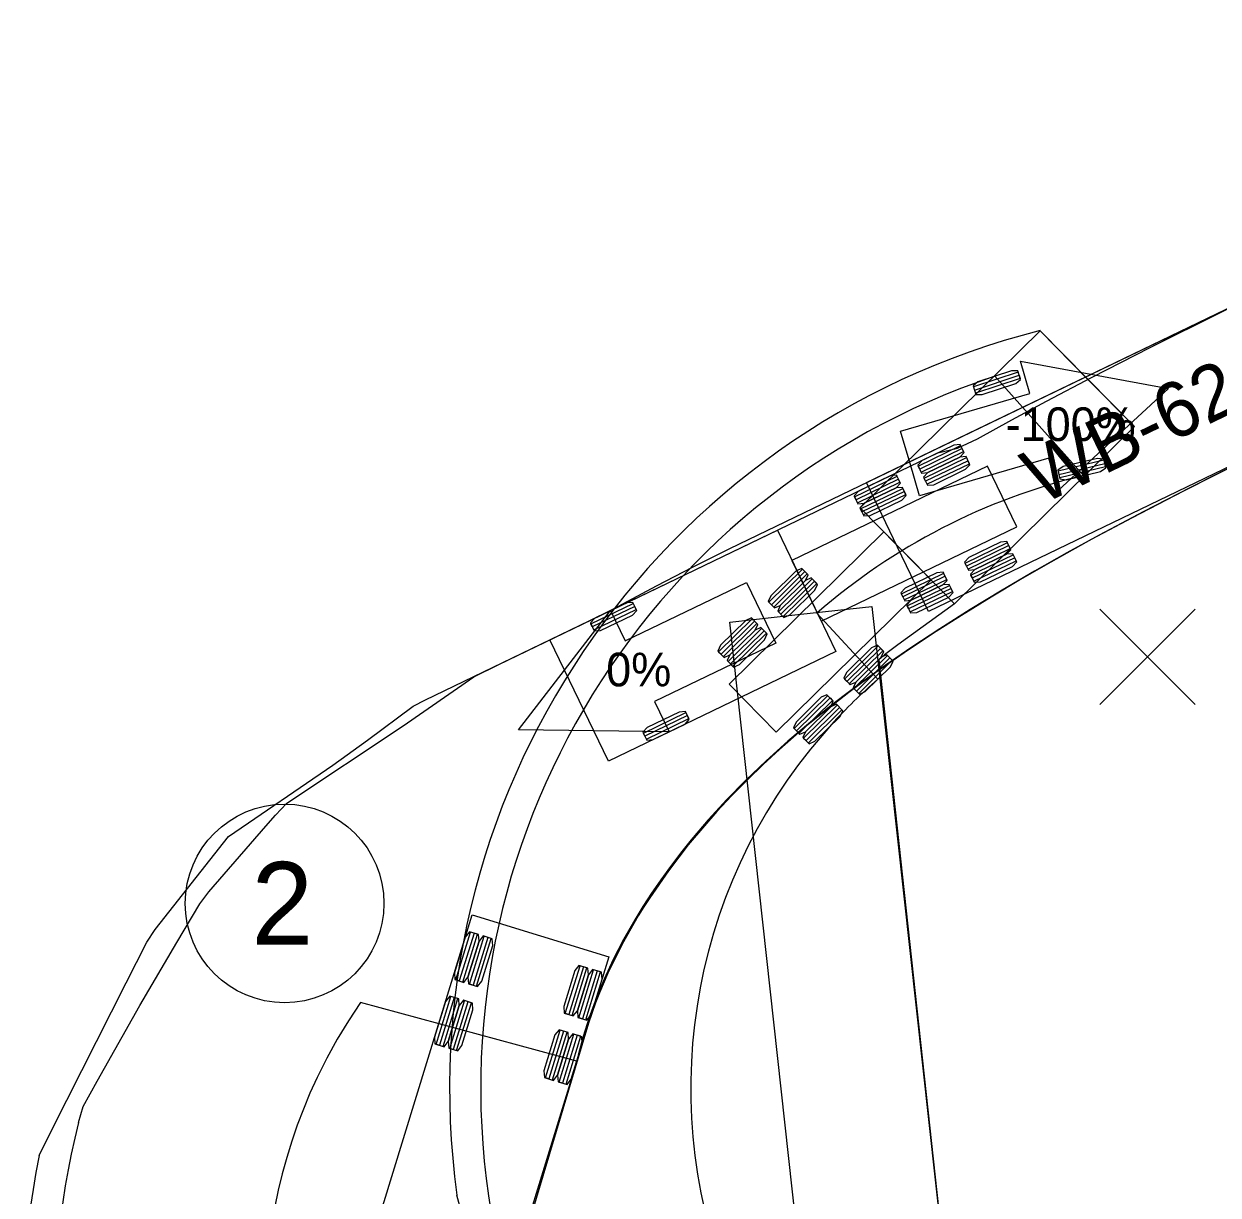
# Model space of a CAD drawing. Extents: x 1475900 to 1484331, y 375914 to 383395.
# Drawn here: x 1478701.4 to 1478772.4, y 379939.6 to 380009.2 of the extents above; entities that cross this region are included whole.
import ezdxf

# ---------------------------------------------------------------- set-up
doc = ezdxf.new("R2010")
doc.units = 0
doc.layers.add('PM_X_Misc', color=7, linetype='Continuous')
doc.layers.add('PM_X_Misc (Construction)', color=7, linetype='Continuous')

# ---------------------------------------------------------------- blocks, each defined once
blk = doc.blocks.new('ATRPTH_1')
at = {"layer": 'PM_X_Misc'}
for points in [[(375830.738, 96498.58), (375830.934, 96498.976), (375832.049, 96501.184), (375832.363, 96501.8), (375832.488, 96501.988), (375833.598, 96503.394), (375835.173, 96504.471), (375835.692, 96504.85), (375836.386, 96505.363), (375836.572, 96505.458), (375839.334, 96506.789), (375840.056, 96507.179), (375840.608, 96507.466), (375841.162, 96507.741), (375854.209, 96514.03), (375855.146, 96512.085)], [(375843.226, 96508.736), (375854.209, 96514.03), (375854.677, 96513.058), (375855.146, 96512.085), (375844.164, 96506.791), (375843.695, 96507.763), (375843.226, 96508.736), (375843.226, 96508.736)], [(375831.333, 96499.078), (375831.4, 96499.318), (375831.611, 96499.7), (375832.258, 96500.842), (375832.814, 96501.795), (375833.161, 96502.378), (375833.297, 96502.56), (375834.16, 96503.55), (375834.306, 96503.716), (375834.474, 96503.896), (375836.234, 96505.064), (375837.299, 96505.804), (375837.675, 96505.989), (375844.306, 96509.186), (375844.598, 96509.254), (375844.902, 96509.394), (375845.422, 96509.684), (375845.942, 96509.965), (375846.631, 96510.327), (375847.509, 96510.775), (375848.583, 96511.308), (375849.894, 96511.949), (375853.637, 96513.754), (375854.574, 96511.809)], [(375848.95, 96509.08), (375848.013, 96508.607), (375847.235, 96508.204), (375846.62, 96507.875), (375846.01, 96507.536), (375845.554, 96507.273), (375845.108, 96507.008), (375844.662, 96506.732), (375844.224, 96506.454), (375843.794, 96506.165), (375843.369, 96505.869), (375842.958, 96505.566), (375842.423, 96505.144), (375842.293, 96505.038), (375841.913, 96504.707), (375841.668, 96504.483), (375841.429, 96504.25), (375841.195, 96504.015), (375840.97, 96503.773), (375840.536, 96503.27), (375840.236, 96502.876), (375839.956, 96502.47), (375839.866, 96502.334), (375839.78, 96502.197), (375839.539, 96501.77), (375839.324, 96501.332), (375839.197, 96501.033), (375839.138, 96500.883), (375839.032, 96500.576), (375836.07, 96490.664)], [(375849.002, 96509.107), (375848.11, 96508.658), (375847.411, 96508.299), (375846.741, 96507.943), (375846.251, 96507.675), (375845.761, 96507.398), (375845.276, 96507.114), (375844.794, 96506.821), (375844.333, 96506.53), (375843.913, 96506.254), (375843.508, 96505.976), (375843.117, 96505.694), (375842.742, 96505.409), (375842.383, 96505.122), (375842.04, 96504.831), (375841.714, 96504.538), (375841.405, 96504.243), (375841.113, 96503.945), (375840.839, 96503.645), (375840.582, 96503.345), (375840.42, 96503.144), (375840.267, 96502.942), (375840.12, 96502.741), (375839.982, 96502.539), (375839.851, 96502.338), (375839.728, 96502.138), (375839.557, 96501.837), (375839.404, 96501.539), (375839.266, 96501.243), (375839.145, 96500.95), (375839.04, 96500.66), (375838.95, 96500.374), (375838.875, 96500.093), (375838.854, 96500.001), (375835.587, 96500.888), (375835.406, 96500.614), (375835.237, 96500.334), (375835.08, 96500.048), (375834.934, 96499.756)], [(375844.052, 96508.894), (375844.693, 96509.203), (375844.671, 96509.249), (375844.03, 96508.94), (375844.008, 96508.986), (375844.648, 96509.295), (375844.641, 96509.31), (375844.546, 96509.302), (375844.066, 96509.07), (375844, 96509.001), (375844.059, 96508.879), (375844.154, 96508.887), (375844.635, 96509.119), (375844.7, 96509.188), (375844.641, 96509.31)], [(375844.14, 96508.711), (375844.781, 96509.02), (375844.759, 96509.066), (375844.118, 96508.757), (375844.096, 96508.803), (375844.737, 96509.112), (375844.729, 96509.127), (375844.635, 96509.119), (375844.154, 96508.887), (375844.089, 96508.818), (375844.148, 96508.696), (375844.242, 96508.704), (375844.723, 96508.936), (375844.788, 96509.005), (375844.729, 96509.127)], [(375842.543, 96506.644), (375845.494, 96508.067), (375845.053, 96508.982), (375842.101, 96507.559), (375842.543, 96506.644)], [(375843.091, 96508.431), (375843.732, 96508.74), (375843.71, 96508.786), (375843.069, 96508.477), (375843.047, 96508.523), (375843.688, 96508.831), (375843.68, 96508.847), (375843.585, 96508.839), (375843.105, 96508.607), (375843.039, 96508.538), (375843.098, 96508.416), (375843.193, 96508.424), (375843.674, 96508.655), (375843.739, 96508.725), (375843.68, 96508.847)], [(375843.179, 96508.248), (375843.82, 96508.557), (375843.798, 96508.603), (375843.157, 96508.294), (375843.135, 96508.339), (375843.776, 96508.648), (375843.768, 96508.664), (375843.674, 96508.655), (375843.193, 96508.424), (375843.128, 96508.355), (375843.187, 96508.233), (375843.281, 96508.241), (375843.762, 96508.472), (375843.827, 96508.542), (375843.768, 96508.664)], [(375838.449, 96506.362), (375841.881, 96508.017), (375842.763, 96506.186), (375839.331, 96504.532), (375838.89, 96505.447), (375838.449, 96506.362), (375838.449, 96506.362)], [(375844.758, 96507.43), (375845.398, 96507.739), (375845.376, 96507.784), (375844.736, 96507.476), (375844.714, 96507.521), (375845.354, 96507.83), (375845.347, 96507.846), (375845.252, 96507.837), (375844.772, 96507.606), (375844.706, 96507.537), (375844.765, 96507.415), (375844.86, 96507.423), (375845.34, 96507.654), (375845.406, 96507.723), (375845.347, 96507.846)], [(375844.846, 96507.247), (375845.487, 96507.556), (375845.465, 96507.601), (375844.824, 96507.293), (375844.802, 96507.338), (375845.443, 96507.647), (375845.435, 96507.662), (375845.34, 96507.654), (375844.86, 96507.423), (375844.795, 96507.354), (375844.853, 96507.232), (375844.948, 96507.24), (375845.429, 96507.471), (375845.494, 96507.54), (375845.435, 96507.662)], [(375843.797, 96506.967), (375844.438, 96507.275), (375844.415, 96507.321), (375843.775, 96507.012), (375843.753, 96507.058), (375844.393, 96507.367), (375844.386, 96507.382), (375844.291, 96507.374), (375843.811, 96507.143), (375843.745, 96507.073), (375843.804, 96506.951), (375843.899, 96506.96), (375844.379, 96507.191), (375844.445, 96507.26), (375844.386, 96507.382)], [(375843.885, 96506.784), (375844.526, 96507.092), (375844.504, 96507.138), (375843.863, 96506.829), (375843.841, 96506.875), (375844.482, 96507.184), (375844.474, 96507.199), (375844.379, 96507.191), (375843.899, 96506.96), (375843.834, 96506.89), (375843.892, 96506.768), (375843.987, 96506.776), (375844.468, 96507.008), (375844.533, 96507.077), (375844.474, 96507.199)], [(375839.11, 96506.512), (375839.75, 96506.821), (375839.728, 96506.866), (375839.088, 96506.558), (375839.066, 96506.603), (375839.706, 96506.912), (375839.699, 96506.927), (375839.604, 96506.919), (375839.124, 96506.688), (375839.058, 96506.619), (375839.117, 96506.497), (375839.212, 96506.505), (375839.692, 96506.736), (375839.758, 96506.805), (375839.699, 96506.927)], [(375839.904, 96504.864), (375840.545, 96505.173), (375840.523, 96505.219), (375839.882, 96504.91), (375839.86, 96504.956), (375840.5, 96505.265), (375840.493, 96505.28), (375840.398, 96505.272), (375839.918, 96505.04), (375839.852, 96504.971), (375839.911, 96504.849), (375840.006, 96504.857), (375840.487, 96505.089), (375840.552, 96505.158), (375840.493, 96505.28)], [(375833.695, 96490.558), (375837.275, 96502.213), (375838.306, 96501.896), (375839.338, 96501.579), (375835.759, 96489.924), (375834.727, 96490.241), (375833.695, 96490.558), (375833.695, 96490.558)], [(375837.132, 96501.197), (375837.354, 96501.919), (375837.302, 96501.935), (375837.08, 96501.213), (375837.029, 96501.229), (375837.251, 96501.951), (375837.233, 96501.956), (375837.171, 96501.877), (375837.005, 96501.335), (375837.012, 96501.234), (375837.149, 96501.192), (375837.211, 96501.271), (375837.378, 96501.813), (375837.371, 96501.914), (375837.233, 96501.956)], [(375837.338, 96501.134), (375837.56, 96501.856), (375837.509, 96501.872), (375837.287, 96501.149), (375837.235, 96501.165), (375837.457, 96501.888), (375837.44, 96501.893), (375837.378, 96501.813), (375837.211, 96501.271), (375837.218, 96501.171), (375837.356, 96501.128), (375837.418, 96501.208), (375837.584, 96501.75), (375837.577, 96501.851), (375837.44, 96501.893)], [(375838.783, 96500.69), (375839.005, 96501.412), (375838.953, 96501.428), (375838.731, 96500.706), (375838.68, 96500.722), (375838.902, 96501.444), (375838.884, 96501.449), (375838.822, 96501.37), (375838.656, 96500.828), (375838.663, 96500.727), (375838.8, 96500.685), (375838.862, 96500.764), (375839.029, 96501.306), (375839.022, 96501.407), (375838.884, 96501.449)], [(375838.989, 96500.627), (375839.211, 96501.349), (375839.16, 96501.365), (375838.938, 96500.642), (375838.886, 96500.658), (375839.108, 96501.381), (375839.091, 96501.386), (375839.029, 96501.306), (375838.862, 96500.764), (375838.869, 96500.664), (375839.007, 96500.621), (375839.069, 96500.701), (375839.235, 96501.243), (375839.228, 96501.344), (375839.091, 96501.386)], [(375836.834, 96500.226), (375837.056, 96500.948), (375837.004, 96500.964), (375836.782, 96500.242), (375836.73, 96500.257), (375836.952, 96500.98), (375836.935, 96500.985), (375836.873, 96500.905), (375836.707, 96500.364), (375836.713, 96500.263), (375836.851, 96500.22), (375836.913, 96500.3), (375837.079, 96500.842), (375837.073, 96500.943), (375836.935, 96500.985)], [(375837.04, 96500.162), (375837.262, 96500.885), (375837.21, 96500.901), (375836.988, 96500.178), (375836.937, 96500.194), (375837.159, 96500.916), (375837.142, 96500.922), (375837.079, 96500.842), (375836.913, 96500.3), (375836.92, 96500.199), (375837.057, 96500.157), (375837.119, 96500.237), (375837.286, 96500.779), (375837.279, 96500.879), (375837.142, 96500.922)], [(375838.485, 96499.719), (375838.707, 96500.441), (375838.655, 96500.457), (375838.433, 96499.735), (375838.382, 96499.75), (375838.603, 96500.473), (375838.586, 96500.478), (375838.524, 96500.398), (375838.358, 96499.857), (375838.364, 96499.756), (375838.502, 96499.713), (375838.564, 96499.793), (375838.73, 96500.335), (375838.724, 96500.436), (375838.586, 96500.478)], [(375838.691, 96499.655), (375838.913, 96500.378), (375838.861, 96500.394), (375838.64, 96499.671), (375838.588, 96499.687), (375838.81, 96500.409), (375838.793, 96500.415), (375838.73, 96500.335), (375838.564, 96499.793), (375838.571, 96499.692), (375838.708, 96499.65), (375838.771, 96499.73), (375838.937, 96500.272), (375838.93, 96500.372), (375838.793, 96500.415)]]:
    blk.add_lwpolyline(points, dxfattribs=at)
for radius, start, end in [(8.159, 154.6205, 211.9328), (11.328, 165.5904, 242.3887), (11.798, 168.6581, 246.6027)]:
    blk.add_arc((375842.305, 96496.259), radius, start, end, dxfattribs=at)
at = {"layer": 'PM_X_Misc (Construction)'}
blk.add_lwpolyline([(375841.636, 96506.771), (375841.856, 96506.313), (375840.026, 96505.431), (375840.246, 96504.973), (375837.975, 96505.006), (375839.364, 96506.804), (375839.585, 96506.346), (375841.415, 96507.228), (375841.636, 96506.771)], dxfattribs=at)
blk.add_circle((375834.443, 96502.384), 1.5, dxfattribs=at)
at = {"layer": 'PM_X_Misc'}
blk.add_text('WB-62 - Interstate Semi-Trailer', height=0.83333, rotation=25.7365, dxfattribs=at).set_placement((375845.858, 96508.39))
at = {"layer": 'PM_X_Misc (Construction)'}
for s, height, p in [('0%', 0.508, (375839.297, 96505.66)), ('2', 1.25, (375833.943, 96501.759))]:
    blk.add_text(s, height=height, dxfattribs=at).set_placement(p)
blk = doc.blocks.new('ATRPTH_4')
at = {"layer": 'PM_X_Misc'}
for p, q in [((375845.162, 96510.34), (375846.501, 96508.841)), ((375842.479, 96506.764), (375843.398, 96505.767)), ((375842.697, 96505.084), (375842.381, 96504.71))]:
    blk.add_line(p, q, dxfattribs=at)
for points in [[(375847.272, 96509.58), (375844.557, 96506.908), (375843.131, 96508.356), (375845.847, 96511.028), (375846.559, 96510.304), (375847.272, 96509.58), (375847.272, 96509.58)], [(375845.847, 96511.028), (375847.272, 96509.58), (375844.557, 96506.908), (375843.698, 96506.286), (375843.5, 96506.134), (375843.411, 96506.061), (375844.536, 96495.758)], [(375845.515, 96510.404), (375844.84, 96510.179), (375844.856, 96510.131), (375845.531, 96510.355), (375845.547, 96510.307), (375844.872, 96510.083), (375844.878, 96510.067), (375844.973, 96510.063), (375845.479, 96510.231), (375845.553, 96510.291), (375845.51, 96510.42), (375845.415, 96510.424), (375844.909, 96510.256), (375844.835, 96510.195), (375844.878, 96510.067)], [(375846.811, 96509.073), (375846.119, 96508.906), (375846.131, 96508.857), (375846.823, 96509.023), (375846.834, 96508.974), (375846.143, 96508.807), (375846.147, 96508.791), (375846.241, 96508.779), (375846.76, 96508.904), (375846.838, 96508.957), (375846.807, 96509.089), (375846.712, 96509.101), (375846.194, 96508.976), (375846.115, 96508.922), (375846.147, 96508.791)], [(375843.488, 96507.994), (375841.153, 96505.695), (375841.865, 96504.971), (375844.201, 96507.27), (375843.488, 96507.994)], [(375842.262, 96507.429), (375841.755, 96506.93), (375841.791, 96506.893), (375842.298, 96507.392), (375842.333, 96507.356), (375841.826, 96506.857), (375841.838, 96506.845), (375841.925, 96506.883), (375842.306, 96507.258), (375842.345, 96507.344), (375842.25, 96507.441), (375842.163, 96507.402), (375841.783, 96507.028), (375841.743, 96506.942), (375841.838, 96506.845)], [(375842.405, 96507.284), (375841.898, 96506.785), (375841.933, 96506.749), (375842.44, 96507.247), (375842.476, 96507.211), (375841.969, 96506.712), (375841.981, 96506.7), (375842.068, 96506.739), (375842.448, 96507.113), (375842.488, 96507.199), (375842.393, 96507.296), (375842.306, 96507.258), (375841.925, 96506.883), (375841.886, 96506.797), (375841.981, 96506.7)], [(375843.309, 96506.866), (375844.644, 96494.748), (375843.571, 96494.629), (375842.498, 96494.511), (375841.163, 96506.63), (375842.236, 96506.748), (375843.309, 96506.866), (375843.309, 96506.866)], [(375841.502, 96506.68), (375840.995, 96506.181), (375841.031, 96506.145), (375841.537, 96506.644), (375841.573, 96506.608), (375841.066, 96506.109), (375841.078, 96506.097), (375841.165, 96506.135), (375841.545, 96506.509), (375841.585, 96506.596), (375841.49, 96506.692), (375841.403, 96506.654), (375841.023, 96506.28), (375840.983, 96506.193), (375841.078, 96506.097)], [(375841.644, 96506.535), (375841.138, 96506.036), (375841.173, 96506), (375841.68, 96506.499), (375841.716, 96506.463), (375841.209, 96505.964), (375841.221, 96505.952), (375841.308, 96505.99), (375841.688, 96506.364), (375841.727, 96506.451), (375841.632, 96506.547), (375841.545, 96506.509), (375841.165, 96506.135), (375841.126, 96506.048), (375841.221, 96505.952)], [(375843.402, 96506.27), (375842.896, 96505.771), (375842.931, 96505.735), (375843.438, 96506.234), (375843.474, 96506.198), (375842.967, 96505.699), (375842.979, 96505.687), (375843.066, 96505.725), (375843.446, 96506.099), (375843.486, 96506.186), (375843.391, 96506.282), (375843.303, 96506.244), (375842.923, 96505.87), (375842.884, 96505.783), (375842.979, 96505.687)], [(375843.545, 96506.125), (375843.038, 96505.626), (375843.074, 96505.59), (375843.581, 96506.089), (375843.616, 96506.053), (375843.109, 96505.554), (375843.121, 96505.542), (375843.208, 96505.58), (375843.589, 96505.954), (375843.628, 96506.041), (375843.533, 96506.137), (375843.446, 96506.099), (375843.066, 96505.725), (375843.026, 96505.638), (375843.121, 96505.542)], [(375842.642, 96505.522), (375842.135, 96505.023), (375842.171, 96504.987), (375842.678, 96505.485), (375842.713, 96505.449), (375842.207, 96504.95), (375842.218, 96504.938), (375842.306, 96504.976), (375842.686, 96505.351), (375842.725, 96505.437), (375842.63, 96505.534), (375842.543, 96505.495), (375842.163, 96505.121), (375842.123, 96505.035), (375842.218, 96504.938)], [(375842.785, 96505.377), (375842.278, 96504.878), (375842.314, 96504.842), (375842.82, 96505.341), (375842.856, 96505.304), (375842.349, 96504.806), (375842.361, 96504.793), (375842.448, 96504.832), (375842.828, 96505.206), (375842.868, 96505.292), (375842.773, 96505.389), (375842.686, 96505.351), (375842.306, 96504.976), (375842.266, 96504.89), (375842.361, 96504.793)], [(375862.923, 96472.293), (375849.554, 96484.734), (375848.585, 96485.638), (375847.743, 96486.425), (375841.812, 96491.952), (375841.524, 96492.238), (375841.239, 96492.531), (375840.935, 96492.849), (375840.315, 96493.428), (375838.243, 96495.352), (375838.125, 96495.537), (375837.473, 96496.687), (375837.387, 96496.895), (375837.105, 96497.761), (375837.044, 96497.981)]]:
    blk.add_lwpolyline(points, dxfattribs=at)
for centre, radius, start, end in [((375848.732, 96499.589), 11.798, 104.155, 187.8308), ((375848.732, 96499.589), 11.328, 108.369, 190.8985), ((375848.732, 96499.589), 9.518, 103.5574, 131.0673), ((375848.732, 96499.589), 8.162, 130.8017, 137.6791), ((375848.733, 96499.589), 8.16, 141.1217, 205.303)]:
    blk.add_arc(centre, radius, start, end, dxfattribs=at)
at = {"layer": 'PM_X_Misc (Construction)'}
for p, q in [((375846.748, 96505.385), (375848.187, 96506.824)), ((375848.187, 96505.385), (375846.748, 96506.824))]:
    blk.add_line(p, q, dxfattribs=at)
blk.add_lwpolyline([(375843.884, 96509.026), (375843.742, 96509.514), (375845.694, 96510.08), (375845.553, 96510.568), (375847.787, 96510.157), (375846.118, 96508.616), (375845.977, 96509.104), (375844.025, 96508.538), (375843.884, 96509.026)], dxfattribs=at)
blk.add_text('-100%', height=0.508, dxfattribs=at).set_placement((375845.327, 96509.363))

msp = doc.modelspace()

# ---------------------------------------------------------------- block references
at = {"layer": 'PM_X_Misc', "xscale": 3.937007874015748, "yscale": 3.937007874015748}
for name in ['ATRPTH_1', 'ATRPTH_4']:
    msp.add_blockref(name, (-946.236, 26.336), dxfattribs=at)

doc.saveas('drawing.dxf')
